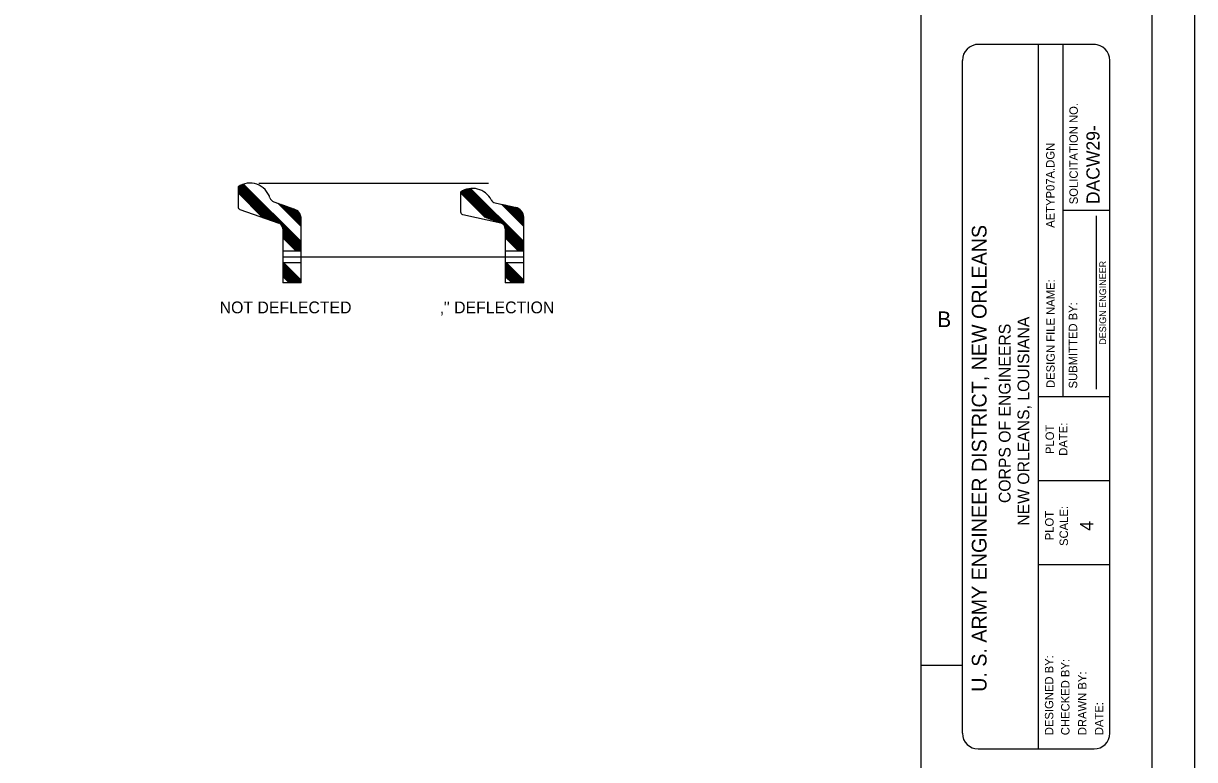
# Model space of a CAD drawing. Extents: x 22369.6 to 22389.4, y 22369.6 to 22386.
# Drawn here: x 22379.648 to 22384.288, y 22372.162 to 22375.08 of the extents above; entities that cross this region are included whole.
import ezdxf

# ---------------------------------------------------------------- set-up
doc = ezdxf.new("R2010")
doc.units = 0
for name, color, linetype in [('Level 1', 7, 'Continuous'), ('Level 10', 7, 'Continuous'), ('Level 2', 7, 'Continuous'), ('Level 4', 7, 'Continuous'), ('Level 7', 7, 'Continuous'), ('Level 9', 7, 'Continuous')]:
    doc.layers.add(name, color=color, linetype=linetype)

msp = doc.modelspace()

# ---------------------------------------------------------------- linework, layer by layer
at = {"layer": 'Level 1'}
for p, q in [((22383.8961, 22374.996), (22383.4201, 22374.996)), ((22383.6681, 22374.996), (22383.6681, 22372.204)), ((22380.4979, 22374.4325), (22380.4979, 22374.3528)), ((22380.4979, 22374.4323), (22380.6322, 22374.298)), ((22380.4979, 22374.4305), (22380.6294, 22374.299)), ((22380.4979, 22374.4286), (22380.6265, 22374.3)), ((22380.4979, 22374.4268), (22380.6237, 22374.301)), ((22380.4979, 22374.4249), (22380.6208, 22374.302)), ((22380.4979, 22374.4231), (22380.618, 22374.303)), ((22380.4989, 22374.4332), (22380.6351, 22374.297)), ((22380.5, 22374.4339), (22380.6379, 22374.296)), ((22380.5011, 22374.4346), (22380.6408, 22374.295)), ((22380.5023, 22374.4353), (22380.6436, 22374.294)), ((22380.5035, 22374.436), (22380.6465, 22374.293)), ((22380.5046, 22374.4366), (22380.6493, 22374.292)), ((22380.5058, 22374.4373), (22380.6522, 22374.291)), ((22380.507, 22374.4379), (22380.655, 22374.29)), ((22380.5083, 22374.4385), (22380.6579, 22374.289)), ((22380.5095, 22374.4391), (22380.6607, 22374.288)), ((22380.5108, 22374.4397), (22380.6648, 22374.2856)), ((22380.5118, 22374.4401), (22380.7479, 22374.204)), ((22380.5128, 22374.4406), (22380.7479, 22374.2054)), ((22380.5138, 22374.441), (22380.7479, 22374.2068)), ((22380.5148, 22374.4414), (22380.7479, 22374.2082)), ((22380.5158, 22374.4418), (22380.7479, 22374.2096)), ((22380.5168, 22374.4421), (22380.7479, 22374.2111)), ((22380.5179, 22374.4425), (22380.7479, 22374.2125)), ((22380.5189, 22374.4429), (22380.7479, 22374.2139)), ((22380.52, 22374.4432), (22380.7479, 22374.2153)), ((22380.5805, 22374.447), (22381.4898, 22374.447)), ((22381.4011, 22374.4221), (22381.5312, 22374.292)), ((22381.4025, 22374.4225), (22381.534, 22374.291)), ((22381.4039, 22374.423), (22381.5369, 22374.29)), ((22381.4053, 22374.4234), (22381.5397, 22374.289)), ((22381.4068, 22374.4237), (22381.5426, 22374.288)), ((22381.4083, 22374.4241), (22381.5467, 22374.2856)), ((22381.4095, 22374.4243), (22381.6298, 22374.204)), ((22381.4106, 22374.4246), (22381.6298, 22374.2054)), ((22381.4118, 22374.4248), (22381.6298, 22374.2068)), ((22381.413, 22374.425), (22381.6298, 22374.2082)), ((22381.4143, 22374.4252), (22381.6298, 22374.2096)), ((22381.4155, 22374.4254), (22381.6298, 22374.2111)), ((22381.4167, 22374.4255), (22381.6298, 22374.2125)), ((22381.418, 22374.4257), (22381.6298, 22374.2139)), ((22381.4193, 22374.4258), (22381.6298, 22374.2153)), ((22380.4979, 22374.4213), (22380.6152, 22374.304)), ((22380.4979, 22374.4194), (22380.6123, 22374.305)), ((22380.4979, 22374.4176), (22380.6095, 22374.306)), ((22380.4979, 22374.4158), (22380.6066, 22374.307)), ((22380.4979, 22374.4139), (22380.6038, 22374.3081)), ((22380.4979, 22374.4121), (22380.6009, 22374.3091)), ((22380.4979, 22374.4102), (22380.5981, 22374.3101)), ((22380.4979, 22374.4084), (22380.5952, 22374.3111)), ((22381.3798, 22374.4117), (22381.3798, 22374.3329)), ((22381.3798, 22374.4102), (22381.48, 22374.3101)), ((22381.3798, 22374.4084), (22381.4771, 22374.3111)), ((22381.38, 22374.4118), (22381.4828, 22374.3091)), ((22381.3811, 22374.4126), (22381.4857, 22374.3081)), ((22381.3823, 22374.4133), (22381.4885, 22374.307)), ((22381.3834, 22374.414), (22381.4913, 22374.306)), ((22381.3845, 22374.4147), (22381.4942, 22374.305)), ((22381.3857, 22374.4154), (22381.497, 22374.304)), ((22381.3869, 22374.416), (22381.4999, 22374.303)), ((22381.3881, 22374.4167), (22381.5027, 22374.302)), ((22381.3893, 22374.4173), (22381.5056, 22374.301)), ((22381.3905, 22374.4179), (22381.5084, 22374.3)), ((22381.3918, 22374.4185), (22381.5113, 22374.299)), ((22381.3931, 22374.4191), (22381.5141, 22374.298)), ((22381.3944, 22374.4196), (22381.517, 22374.297)), ((22381.3957, 22374.4201), (22381.5198, 22374.296)), ((22381.397, 22374.4207), (22381.5226, 22374.295)), ((22381.3983, 22374.4212), (22381.5255, 22374.294)), ((22381.3997, 22374.4216), (22381.5283, 22374.293)), ((22380.5049, 22374.343), (22380.6594, 22374.2884)), ((22380.6391, 22374.3729), (22380.7201, 22374.3443)), ((22380.7479, 22374.2751), (22380.6562, 22374.3669)), ((22380.7479, 22374.2765), (22380.6583, 22374.3661)), ((22380.7479, 22374.2779), (22380.6605, 22374.3654)), ((22380.7479, 22374.2794), (22380.6627, 22374.3646)), ((22380.7479, 22374.2808), (22380.6649, 22374.3638)), ((22380.7479, 22374.2822), (22380.6671, 22374.363)), ((22380.7479, 22374.2836), (22380.6693, 22374.3623)), ((22380.7479, 22374.285), (22380.6714, 22374.3615)), ((22380.7479, 22374.2864), (22380.6736, 22374.3607)), ((22380.7479, 22374.2878), (22380.6758, 22374.36)), ((22380.7479, 22374.2893), (22380.678, 22374.3592)), ((22380.7479, 22374.2907), (22380.6802, 22374.3584)), ((22380.7479, 22374.2921), (22380.6824, 22374.3576)), ((22380.7479, 22374.2935), (22380.6845, 22374.3569)), ((22380.7479, 22374.2949), (22380.6868, 22374.3561)), ((22380.7479, 22374.2963), (22380.6889, 22374.3553)), ((22380.7479, 22374.2977), (22380.6911, 22374.3546)), ((22380.7479, 22374.2991), (22380.6933, 22374.3538)), ((22380.7479, 22374.3006), (22380.6955, 22374.353)), ((22380.6977, 22374.3522), (22380.7479, 22374.302)), ((22380.6998, 22374.3515), (22380.7479, 22374.3034)), ((22380.702, 22374.3507), (22380.7479, 22374.3048)), ((22380.7042, 22374.3499), (22380.7479, 22374.3062)), ((22380.7064, 22374.3491), (22380.7479, 22374.3076)), ((22380.7086, 22374.3484), (22380.7477, 22374.3093)), ((22380.7108, 22374.3476), (22380.7475, 22374.3109)), ((22380.7129, 22374.3468), (22380.7472, 22374.3126)), ((22380.7151, 22374.3461), (22380.7469, 22374.3144)), ((22380.7173, 22374.3453), (22380.7464, 22374.3163)), ((22380.7195, 22374.3445), (22380.7457, 22374.3183)), ((22380.7217, 22374.3438), (22380.7449, 22374.3205)), ((22380.7243, 22374.3426), (22380.7438, 22374.3231)), ((22380.7273, 22374.341), (22380.7422, 22374.326)), ((22380.7316, 22374.3381), (22380.7393, 22374.3303)), ((22381.5165, 22374.3687), (22381.5972, 22374.3506)), ((22381.6298, 22374.2751), (22381.5419, 22374.363)), ((22381.6298, 22374.2765), (22381.5437, 22374.3626)), ((22381.6298, 22374.2779), (22381.5455, 22374.3622)), ((22381.6298, 22374.2794), (22381.5474, 22374.3618)), ((22381.6298, 22374.2808), (22381.5492, 22374.3614)), ((22381.6298, 22374.2822), (22381.551, 22374.361)), ((22381.6298, 22374.2836), (22381.5528, 22374.3606)), ((22381.6298, 22374.285), (22381.5546, 22374.3602)), ((22381.6298, 22374.2864), (22381.5565, 22374.3598)), ((22381.6298, 22374.2878), (22381.5583, 22374.3593)), ((22381.6298, 22374.2893), (22381.5601, 22374.3589)), ((22381.6298, 22374.2907), (22381.562, 22374.3585)), ((22381.6298, 22374.2921), (22381.5642, 22374.3576)), ((22381.6298, 22374.2935), (22381.5656, 22374.3577)), ((22381.6298, 22374.2949), (22381.5674, 22374.3573)), ((22381.6298, 22374.2963), (22381.5692, 22374.3569)), ((22381.6298, 22374.2977), (22381.571, 22374.3565)), ((22381.6298, 22374.2991), (22381.5729, 22374.3561)), ((22381.6298, 22374.3006), (22381.5747, 22374.3557)), ((22381.5765, 22374.3553), (22381.6298, 22374.302)), ((22381.5783, 22374.3549), (22381.6298, 22374.3034)), ((22381.5802, 22374.3545), (22381.6298, 22374.3048)), ((22381.582, 22374.354), (22381.6298, 22374.3062)), ((22381.5838, 22374.3536), (22381.6298, 22374.3076)), ((22381.5856, 22374.3532), (22381.6296, 22374.3093)), ((22381.5874, 22374.3528), (22381.6298, 22374.3105)), ((22381.5893, 22374.3524), (22381.6298, 22374.3119)), ((22381.5911, 22374.352), (22381.6297, 22374.3134)), ((22381.5929, 22374.3516), (22381.6295, 22374.315)), ((22381.5947, 22374.3512), (22381.6293, 22374.3167)), ((22381.5966, 22374.3508), (22381.6289, 22374.3184)), ((22381.5984, 22374.3503), (22381.6285, 22374.3203)), ((22381.6003, 22374.3498), (22381.628, 22374.3222)), ((22381.6025, 22374.3491), (22381.6273, 22374.3243)), ((22381.6056, 22374.3478), (22381.626, 22374.3274)), ((22381.6095, 22374.3457), (22381.6239, 22374.3314)), ((22380.7479, 22374.0511), (22380.7479, 22374.305)), ((22381.388, 22374.3228), (22381.5386, 22374.289)), ((22381.6298, 22374.0511), (22381.6298, 22374.31)), ((22380.6709, 22374.2796), (22380.7479, 22374.2026)), ((22380.6728, 22374.2763), (22380.7479, 22374.2011)), ((22380.6737, 22374.2739), (22380.7479, 22374.1998)), ((22380.6743, 22374.2719), (22380.7479, 22374.1983)), ((22380.675, 22374.2698), (22380.7479, 22374.1969)), ((22380.675, 22374.2684), (22380.7479, 22374.1955)), ((22380.675, 22374.267), (22380.7479, 22374.1941)), ((22380.675, 22374.2663), (22380.675, 22374.0511)), ((22380.675, 22374.2656), (22380.7479, 22374.1927)), ((22380.675, 22374.2642), (22380.7479, 22374.1913)), ((22380.675, 22374.2628), (22380.7479, 22374.1898)), ((22380.675, 22374.2613), (22380.7479, 22374.1884)), ((22380.675, 22374.2599), (22380.7479, 22374.187)), ((22380.675, 22374.2585), (22380.7479, 22374.1856)), ((22380.675, 22374.2571), (22380.7479, 22374.1842)), ((22380.675, 22374.2557), (22380.7479, 22374.1828)), ((22380.675, 22374.2543), (22380.7479, 22374.1814)), ((22380.675, 22374.2529), (22380.7479, 22374.1799)), ((22380.675, 22374.2514), (22380.7479, 22374.1785)), ((22380.675, 22374.25), (22380.7463, 22374.1787)), ((22380.675, 22374.2486), (22380.7449, 22374.1787)), ((22380.675, 22374.2472), (22380.7435, 22374.1787)), ((22380.675, 22374.2458), (22380.7421, 22374.1787)), ((22380.675, 22374.2444), (22380.7406, 22374.1787)), ((22380.675, 22374.243), (22380.7392, 22374.1787)), ((22380.675, 22374.2415), (22380.7378, 22374.1787)), ((22380.675, 22374.2401), (22380.7364, 22374.1787)), ((22380.675, 22374.2387), (22380.735, 22374.1787)), ((22380.675, 22374.2373), (22380.7336, 22374.1787)), ((22381.5528, 22374.2796), (22381.6298, 22374.2026)), ((22381.5547, 22374.2763), (22381.6298, 22374.2011)), ((22381.5556, 22374.2739), (22381.6298, 22374.1998)), ((22381.5562, 22374.2719), (22381.6298, 22374.1983)), ((22381.5569, 22374.2698), (22381.6298, 22374.1969)), ((22381.5569, 22374.2684), (22381.6298, 22374.1955)), ((22381.5569, 22374.267), (22381.6298, 22374.1941)), ((22381.5569, 22374.2662), (22381.5569, 22374.0511)), ((22381.5569, 22374.2656), (22381.6298, 22374.1927)), ((22381.5569, 22374.2642), (22381.6298, 22374.1913)), ((22381.5569, 22374.2628), (22381.6298, 22374.1898)), ((22381.5569, 22374.2613), (22381.6298, 22374.1884)), ((22381.5569, 22374.2599), (22381.6298, 22374.187)), ((22381.5569, 22374.2585), (22381.6298, 22374.1856)), ((22381.5569, 22374.2571), (22381.6298, 22374.1842)), ((22381.5569, 22374.2557), (22381.6298, 22374.1828)), ((22381.5569, 22374.2543), (22381.6298, 22374.1814)), ((22381.5569, 22374.2529), (22381.6298, 22374.1799)), ((22381.5569, 22374.2514), (22381.6298, 22374.1785)), ((22381.5569, 22374.25), (22381.6282, 22374.1787)), ((22381.5569, 22374.2486), (22381.6268, 22374.1787)), ((22381.5569, 22374.2472), (22381.6254, 22374.1787)), ((22381.5569, 22374.2458), (22381.6239, 22374.1787)), ((22381.5569, 22374.2444), (22381.6225, 22374.1787)), ((22381.5569, 22374.243), (22381.6211, 22374.1787)), ((22381.5569, 22374.2415), (22381.6197, 22374.1787)), ((22381.5569, 22374.2401), (22381.6183, 22374.1787)), ((22381.5569, 22374.2387), (22381.6169, 22374.1787)), ((22381.5569, 22374.2373), (22381.6154, 22374.1787)), ((22380.675, 22374.2359), (22380.7322, 22374.1787)), ((22380.675, 22374.2345), (22380.7307, 22374.1787)), ((22380.675, 22374.2331), (22380.7293, 22374.1787)), ((22380.675, 22374.2316), (22380.7279, 22374.1787)), ((22380.675, 22374.2302), (22380.7265, 22374.1787)), ((22381.5569, 22374.2359), (22381.614, 22374.1787)), ((22381.5569, 22374.2345), (22381.6126, 22374.1787)), ((22381.5569, 22374.2331), (22381.6112, 22374.1787)), ((22381.5569, 22374.2316), (22381.6098, 22374.1787)), ((22381.5569, 22374.2302), (22381.6084, 22374.1787)), ((22380.675, 22374.1787), (22380.7479, 22374.1787)), ((22380.675, 22374.1553), (22381.6298, 22374.1553)), ((22381.5569, 22374.1787), (22381.6298, 22374.1787)), ((22380.675, 22374.1319), (22380.7479, 22374.1319)), ((22380.675, 22374.1319), (22380.7479, 22374.059)), ((22380.675, 22374.1305), (22380.7479, 22374.0576)), ((22380.675, 22374.1291), (22380.7479, 22374.0562)), ((22380.675, 22374.1277), (22380.7479, 22374.0547)), ((22380.675, 22374.1262), (22380.7479, 22374.0533)), ((22380.675, 22374.1248), (22380.7479, 22374.0519)), ((22380.675, 22374.1234), (22380.7473, 22374.0511)), ((22380.675, 22374.122), (22380.7459, 22374.0511)), ((22380.675, 22374.1206), (22380.7444, 22374.0511)), ((22380.675, 22374.1192), (22380.743, 22374.0511)), ((22380.675, 22374.1178), (22380.7416, 22374.0511)), ((22380.675, 22374.1163), (22380.7402, 22374.0511)), ((22380.675, 22374.1149), (22380.7388, 22374.0511)), ((22380.675, 22374.1135), (22380.7374, 22374.0511)), ((22380.675, 22374.1121), (22380.736, 22374.0511)), ((22380.675, 22374.1107), (22380.7345, 22374.0511)), ((22380.675, 22374.1093), (22380.7331, 22374.0511)), ((22380.675, 22374.1078), (22380.7317, 22374.0511)), ((22380.675, 22374.1064), (22380.7303, 22374.0511)), ((22380.675, 22374.105), (22380.7289, 22374.0511)), ((22380.675, 22374.1036), (22380.7275, 22374.0511)), ((22380.675, 22374.1022), (22380.7261, 22374.0511)), ((22380.675, 22374.1008), (22380.7247, 22374.0511)), ((22380.675, 22374.0994), (22380.7232, 22374.0511)), ((22380.675, 22374.098), (22380.7218, 22374.0511)), ((22380.6764, 22374.1319), (22380.7479, 22374.0604)), ((22380.6779, 22374.1319), (22380.7479, 22374.0618)), ((22380.678, 22374.1319), (22380.7479, 22374.0619)), ((22381.5569, 22374.1319), (22381.6298, 22374.1319)), ((22381.5569, 22374.1319), (22381.6298, 22374.059)), ((22381.5569, 22374.1305), (22381.6298, 22374.0576)), ((22381.5569, 22374.1291), (22381.6298, 22374.0562)), ((22381.5569, 22374.1277), (22381.6298, 22374.0547)), ((22381.5569, 22374.1262), (22381.6298, 22374.0533)), ((22381.5569, 22374.1248), (22381.6298, 22374.0519)), ((22381.5569, 22374.1234), (22381.6292, 22374.0511)), ((22381.5569, 22374.122), (22381.6277, 22374.0511)), ((22381.5569, 22374.1206), (22381.6263, 22374.0511)), ((22381.5569, 22374.1192), (22381.6249, 22374.0511)), ((22381.5569, 22374.1178), (22381.6235, 22374.0511)), ((22381.5569, 22374.1163), (22381.6221, 22374.0511)), ((22381.5569, 22374.1149), (22381.6207, 22374.0511)), ((22381.5569, 22374.1135), (22381.6193, 22374.0511)), ((22381.5569, 22374.1121), (22381.6178, 22374.0511)), ((22381.5569, 22374.1107), (22381.6164, 22374.0511)), ((22381.5569, 22374.1093), (22381.615, 22374.0511)), ((22381.5569, 22374.1078), (22381.6136, 22374.0511)), ((22381.5569, 22374.1064), (22381.6122, 22374.0511)), ((22381.5569, 22374.105), (22381.6108, 22374.0511)), ((22381.5569, 22374.1036), (22381.6094, 22374.0511)), ((22381.5569, 22374.1022), (22381.608, 22374.0511)), ((22381.5569, 22374.1008), (22381.6065, 22374.0511)), ((22381.5569, 22374.0994), (22381.6051, 22374.0511)), ((22381.5569, 22374.098), (22381.6037, 22374.0511)), ((22381.5583, 22374.1319), (22381.6298, 22374.0604)), ((22381.5597, 22374.1319), (22381.6298, 22374.0618)), ((22381.5598, 22374.1319), (22381.6298, 22374.0619)), ((22380.675, 22374.0965), (22380.7204, 22374.0511)), ((22380.675, 22374.0951), (22380.719, 22374.0511)), ((22380.675, 22374.0937), (22380.7176, 22374.0511)), ((22380.675, 22374.0923), (22380.7162, 22374.0511)), ((22380.675, 22374.0909), (22380.7148, 22374.0511)), ((22380.675, 22374.0895), (22380.7133, 22374.0511)), ((22380.675, 22374.0881), (22380.7119, 22374.0511)), ((22380.675, 22374.0866), (22380.7105, 22374.0511)), ((22380.675, 22374.0852), (22380.7091, 22374.0511)), ((22380.675, 22374.0838), (22380.7077, 22374.0511)), ((22380.675, 22374.0824), (22380.7063, 22374.0511)), ((22380.675, 22374.081), (22380.7049, 22374.0511)), ((22380.675, 22374.0796), (22380.7034, 22374.0511)), ((22380.675, 22374.0782), (22380.702, 22374.0511)), ((22380.675, 22374.0767), (22380.7006, 22374.0511)), ((22380.7479, 22374.0511), (22380.675, 22374.0511)), ((22381.5569, 22374.0965), (22381.6023, 22374.0511)), ((22381.5569, 22374.0951), (22381.6009, 22374.0511)), ((22381.5569, 22374.0937), (22381.5995, 22374.0511)), ((22381.5569, 22374.0923), (22381.5981, 22374.0511)), ((22381.5569, 22374.0909), (22381.5966, 22374.0511)), ((22381.5569, 22374.0895), (22381.5952, 22374.0511)), ((22381.5569, 22374.0881), (22381.5938, 22374.0511)), ((22381.5569, 22374.0866), (22381.5924, 22374.0511)), ((22381.5569, 22374.0852), (22381.591, 22374.0511)), ((22381.5569, 22374.0838), (22381.5896, 22374.0511)), ((22381.5569, 22374.0824), (22381.5881, 22374.0511)), ((22381.5569, 22374.081), (22381.5867, 22374.0511)), ((22381.5569, 22374.0796), (22381.5853, 22374.0511)), ((22381.5569, 22374.0782), (22381.5839, 22374.0511)), ((22381.5569, 22374.0767), (22381.5825, 22374.0511)), ((22381.6298, 22374.0511), (22381.5569, 22374.0511))]:
    msp.add_line(p, q, dxfattribs=at)
msp.add_lwpolyline([(22369.6213, 22380.9546), (22384.2881, 22380.9546), (22384.2881, 22369.6213), (22369.6213, 22369.6213)], close=True, dxfattribs=at)
for points in [[(22383.8896, 22374.996), (22383.4306, 22374.996)], [(22383.3681, 22372.2665), (22383.3681, 22374.9335)], [(22383.9521, 22372.2665), (22383.9521, 22374.9335)], [(22383.4306, 22372.204), (22383.8896, 22372.204)]]:
    msp.add_lwpolyline(points, dxfattribs=at)
for centre, radius, start, end in [((22383.4306, 22374.9335), 0.0625, 90, 180), ((22383.8896, 22374.9335), 0.0625, 0, 90), ((22380.5448, 22374.3636), 0.0833, 17.0995, 124.2345), ((22381.4267, 22374.3428), 0.0833, 27.1705, 124.2289), ((22380.6469, 22374.395), 0.0234, 197.0995, 250.5613), ((22381.5217, 22374.3916), 0.0234, 207.1705, 257.3835), ((22380.5083, 22374.3528), 0.0104, 180, 250.5607), ((22380.7063, 22374.305), 0.0417, 0, 70.5605), ((22381.3902, 22374.3329), 0.0104, 180, 257.3821), ((22381.5881, 22374.31), 0.0417, 0, 77.3827), ((22380.6516, 22374.2663), 0.0234, 0, 70.56), ((22381.5335, 22374.2662), 0.0234, 0, 77.3806), ((22383.4306, 22372.2665), 0.0625, 180, 270), ((22383.8896, 22372.2665), 0.0625, 270, 0)]:
    msp.add_arc(centre, radius, start, end, dxfattribs=at)
at = {"layer": 'Level 10'}
msp.add_line((22383.2041, 22372.536), (22383.3681, 22372.536), dxfattribs=at)
at = {"layer": 'Level 2'}
for p, q in [((22383.7664, 22374.996), (22383.7664, 22373.6)), ((22383.9521, 22374.3388), (22383.7664, 22374.3388)), ((22383.9001, 22373.6302), (22383.9001, 22374.3173)), ((22383.9521, 22373.6), (22383.6681, 22373.6)), ((22383.9521, 22373.2666), (22383.6681, 22373.2666)), ((22383.9521, 22372.9333), (22383.6681, 22372.9333))]:
    msp.add_line(p, q, dxfattribs=at)
at = {"layer": 'Level 9'}
msp.add_line((22384.1201, 22369.788), (22384.1201, 22380.788), dxfattribs=at)
msp.add_lwpolyline([(22383.2041, 22369.788), (22383.2041, 22380.788)], dxfattribs=at)

# ---------------------------------------------------------------- texts
at = {"layer": 'Level 1'}
for s, height, p in [('SOLICITATION NO.', 0.033336, (22383.8255, 22374.3631)), ('AETYP07A.DGN', 0.033333, (22383.7331, 22374.2697)), ('U. S. ARMY ENGINEER DISTRICT, NEW ORLEANS', 0.058333, (22383.4638, 22372.4305)), ('DESIGN ENGINEER', 0.026664, (22383.9376, 22373.8061)), ('DESIGN FILE NAME:', 0.033336, (22383.7341, 22373.6348)), ('SUBMITTED BY:', 0.033336, (22383.823, 22373.6331)), ('PLOT', 0.03334, (22383.731, 22373.373)), ('DATE:', 0.03334, (22383.7842, 22373.3661)), ('PLOT', 0.03334, (22383.7294, 22373.0313)), ('SCALE:', 0.03334, (22383.7865, 22373.0087)), ('DESIGNED BY:', 0.033336, (22383.7284, 22372.2586)), ('CHECKED BY:', 0.033336, (22383.7924, 22372.2586)), ('DRAWN BY:', 0.03334, (22383.8597, 22372.2586)), ('DATE:', 0.03334, (22383.9263, 22372.2586))]:
    msp.add_text(s, height=height, rotation=90, dxfattribs=at).set_placement(p)
msp.add_text('B', height=0.0624, dxfattribs=at).set_placement((22383.2681, 22373.876))
at = {"layer": 'Level 4'}
for s, p in [('NOT DEFLECTED', (22380.4251, 22373.9308)), ("‚'' DEFLECTION", (22381.2989, 22373.9308))]:
    msp.add_text(s, height=0.046875, dxfattribs=at).set_placement(p)
at = {"layer": 'Level 7'}
for s, height, p in [('DACW29-', 0.052, (22383.9116, 22374.3635)), ('NEW ORLEANS, LOUISIANA', 0.046667, (22383.6333, 22373.0888)), ('CORPS OF ENGINEERS', 0.046667, (22383.559, 22373.1787)), ('4', 0.052, (22383.8863, 22373.0691))]:
    msp.add_text(s, height=height, rotation=90, dxfattribs=at).set_placement(p)

doc.saveas('drawing.dxf')
